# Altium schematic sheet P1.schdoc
size 297 x 209 mm; Symbol: Drawing-Symbol_A4; @Project Name: pcbwatch; @Page Count: 1; @Update Date: 2026-05-27; @Create Date: 2026-05-20; @Schematic Name: Schematic1; @Page No: 1; @Page Name: P1; Company: EasyEDA.com; Version: V1.0; Page Size: A4; @Create Time: 13:10:33; @Update Time: 00:51:18; Border: 1; Width: 1170; Height: 825; Region Start: 1; X Region Count: 6; Y Region Count: 4; Blade Width: 10; Title Block Position: 3; @Board Name: Board1; Device: Drawing-Symbol_A4
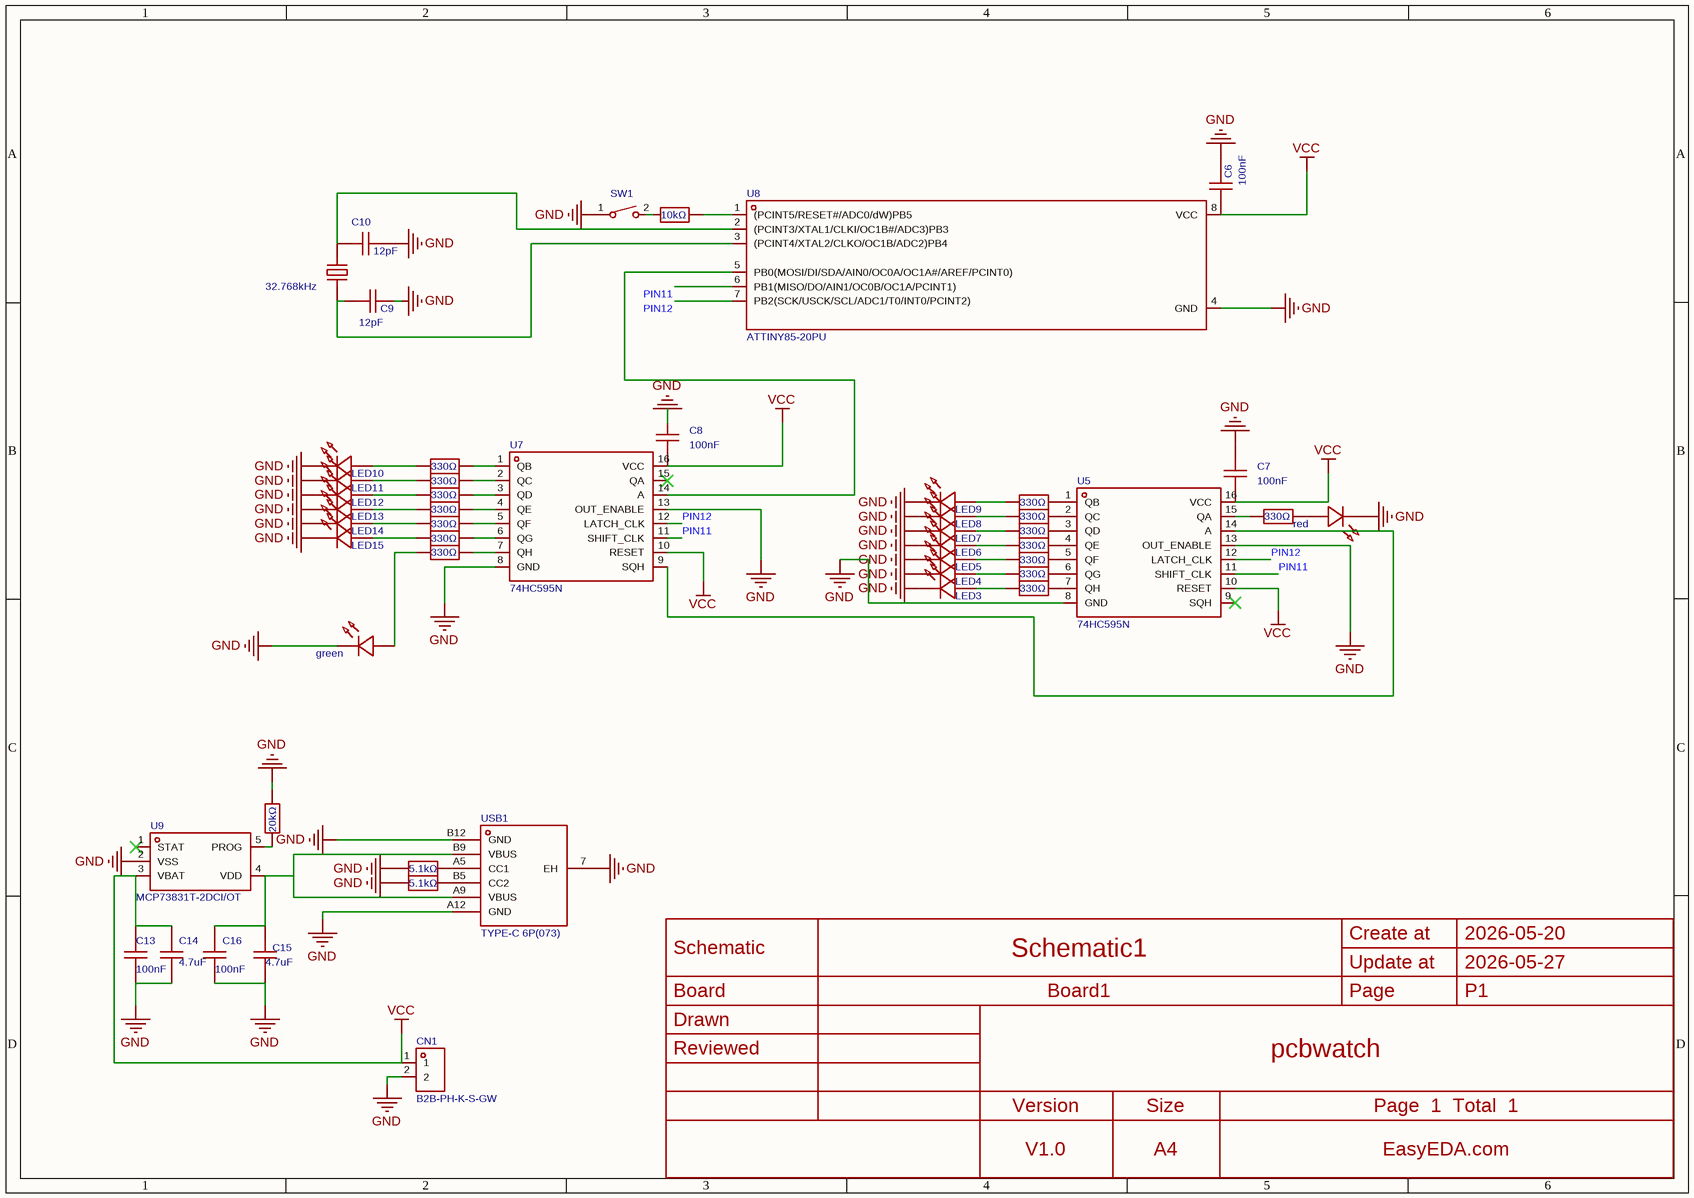
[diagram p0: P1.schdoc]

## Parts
C6  100nF  [CAP-TH_L5.8-W2.4-P2.54-D0.6]
C7  100nF  [CAP-TH_L5.8-W2.4-P2.54-D0.6]
C8  100nF  [CAP-TH_L5.8-W2.4-P2.54-D0.6]
C9  12pF  [CAP-TH_L5.8-W2.4-P2.54-D0.6]
C10  12pF  [CAP-TH_L5.8-W2.4-P2.54-D0.6]
C13  100nF  [CAP-TH_L5.8-W2.4-P2.54-D0.6]
C14  4.7uF  [CAP-TH_L5.8-W2.4-P2.54-D0.6]
C15  4.7uF  [CAP-TH_L5.8-W2.4-P2.54-D0.6]
C16  100nF  [CAP-TH_L5.8-W2.4-P2.54-D0.6]
CN1  B2B-PH-K-S-GW  [CONN-TH_B2B-PH-K-S]
green  TJ-S2012EX8T5ALC2R-A5  [LED0805-RD]  (value not drawn)
LED3  TJ-S2012EX8T5ALC2R-A5  [LED0805-RD]  (value not drawn)
LED4  TJ-S2012EX8T5ALC2R-A5  [LED0805-RD]  (value not drawn)
LED5  TJ-S2012EX8T5ALC2R-A5  [LED0805-RD]  (value not drawn)
LED6  TJ-S2012EX8T5ALC2R-A5  [LED0805-RD]  (value not drawn)
LED7  TJ-S2012EX8T5ALC2R-A5  [LED0805-RD]  (value not drawn)
LED8  TJ-S2012EX8T5ALC2R-A5  [LED0805-RD]  (value not drawn)
LED9  TJ-S2012EX8T5ALC2R-A5  [LED0805-RD]  (value not drawn)
LED10  TJ-S2012EX8T5ALC2R-A5  [LED0805-RD]  (value not drawn)
LED11  TJ-S2012EX8T5ALC2R-A5  [LED0805-RD]  (value not drawn)
LED12  TJ-S2012EX8T5ALC2R-A5  [LED0805-RD]  (value not drawn)
LED13  TJ-S2012EX8T5ALC2R-A5  [LED0805-RD]  (value not drawn)
LED14  TJ-S2012EX8T5ALC2R-A5  [LED0805-RD]  (value not drawn)
LED15  TJ-S2012EX8T5ALC2R-A5  [LED0805-RD]  (value not drawn)
R20  330Ω  [RES-TH_BD2.3-L6.5-P10.50-D0.5]
R21  330Ω  [RES-TH_BD2.3-L6.5-P10.50-D0.5]
R22  330Ω  [RES-TH_BD2.3-L6.5-P10.50-D0.5]
R23  330Ω  [RES-TH_BD2.3-L6.5-P10.50-D0.5]
R24  330Ω  [RES-TH_BD2.3-L6.5-P10.50-D0.5]
R25  330Ω  [RES-TH_BD2.3-L6.5-P10.50-D0.5]
R26  330Ω  [RES-TH_BD2.3-L6.5-P10.50-D0.5]
R27  330Ω  [RES-TH_BD2.3-L6.5-P10.50-D0.5]
R28  330Ω  [RES-TH_BD2.3-L6.5-P10.50-D0.5]
R29  330Ω  [RES-TH_BD2.3-L6.5-P10.50-D0.5]
R30  330Ω  [RES-TH_BD2.3-L6.5-P10.50-D0.5]
R31  330Ω  [RES-TH_BD2.3-L6.5-P10.50-D0.5]
R32  330Ω  [RES-TH_BD2.3-L6.5-P10.50-D0.5]
R33  330Ω  [RES-TH_BD2.3-L6.5-P10.50-D0.5]
R34  330Ω  [RES-TH_BD2.3-L6.5-P10.50-D0.5]
R36  10kΩ  [RES-TH_BD2.3-L6.5-P10.50-D0.5]
R40  20kΩ  [RES-TH_BD2.3-L6.5-P10.50-D0.5]
R41  5.1kΩ  [RES-TH_BD2.3-L6.5-P10.50-D0.5]
R42  5.1kΩ  [RES-TH_BD2.3-L6.5-P10.50-D0.5]
red  TJ-S2012EX8T5ALC2R-A5  [LED0805-RD]  (value not drawn)
SW1  HX 3x4x2-2P-1.6N TACTILE SWITCH  [KEY-SMD_L4.0-W3.0-LS4.9-1]  (value not drawn)
U5  74HC595N  [DIP-16_L19.8-W6.5-P2.54-LS7.6-BL]
U7  74HC595N  [DIP-16_L19.8-W6.5-P2.54-LS7.6-BL]
U8  ATTINY85-20PU  [PDIP-8_L9.3-W6.4-P2.54-LS7.9-BL-1]
U9  MCP73831T-2DCI/OT  [SOT-23-5_L2.9-W1.6-P0.95-LS2.8-BL]
USB1  TYPE-C 6P(073)  [TYPE-C-SMD_TYPE-C-6P-073]
X1  32.768kHz  [OSC-TH_BD2.0-P0.70-D0.3]

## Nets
GND: C6.2 C7.2 C8.1 C9.1 C10.1 C13.2 C14.2 C15.2 C16.2 CN1.2 green.1(C) LED3.1(C) LED4.1(C) LED5.1(C) LED6.1(C) LED7.1(C) LED8.1(C) LED9.1(C) LED10.1(C) LED11.1(C) LED12.1(C) LED13.1(C) LED14.1(C) LED15.1(C) R40.2 R41.2 R42.2 red.1(C) SW1.1 U5.8(GND) U5.13(OUT_ENABLE) U7.8(GND) U7.13(OUT_ENABLE) U8.4(GND) U9.2(VSS) USB1.7(EH) USB1.A12(GND) USB1.B12(GND)
VCC: C6.1 C7.1 C8.2 C13.1 C14.1 CN1.1 U5.10(RESET) U5.16(VCC) U7.10(RESET) U7.16(VCC) U8.8(VCC) U9.3(VBAT)
PIN11: U5.11(SHIFT_CLK) U7.11(SHIFT_CLK) U8.6(PB1(MISO/DO/AIN1/OC0B/OC1A/PCINT1))
PIN12: U5.12(LATCH_CLK) U7.12(LATCH_CLK) U8.7(PB2(SCK/USCK/SCL/ADC1/T0/INT0/PCINT2))
NetC9_2: C9.2 U8.3((PCINT4/XTAL2/CLKO/OC1B/ADC2)PB4) X1.1
NetC10_2: C10.2 U8.2((PCINT3/XTAL1/CLKI/OC1B#/ADC3)PB3) X1.2
NetC15_1: C15.1 C16.1 U9.4(VDD) USB1.A9(VBUS) USB1.B9(VBUS)
Netgreen_2: green.2(A) R26.1
NetLED3_2: LED3.2(A) R33.1
NetLED4_2: LED4.2(A) R32.1
NetLED5_2: LED5.2(A) R31.1
NetLED6_2: LED6.2(A) R30.1
NetLED7_2: LED7.2(A) R29.1
NetLED8_2: LED8.2(A) R28.1
NetLED9_2: LED9.2(A) R27.1
NetLED10_2: LED10.2(A) R20.1
NetLED11_2: LED11.2(A) R21.1
NetLED12_2: LED12.2(A) R22.1
NetLED13_2: LED13.2(A) R23.1
NetLED14_2: LED14.2(A) R24.1
NetLED15_2: LED15.2(A) R25.1
NetR20_2: R20.2 U7.1(QB)
NetR21_2: R21.2 U7.2(QC)
NetR22_2: R22.2 U7.3(QD)
NetR23_2: R23.2 U7.4(QE)
NetR24_2: R24.2 U7.5(QF)
NetR25_2: R25.2 U7.6(QG)
NetR26_2: R26.2 U7.7(QH)
NetR27_2: R27.2 U5.1(QB)
NetR28_2: R28.2 U5.2(QC)
NetR29_2: R29.2 U5.3(QD)
NetR30_2: R30.2 U5.4(QE)
NetR31_2: R31.2 U5.5(QF)
NetR32_2: R32.2 U5.6(QG)
NetR33_2: R33.2 U5.7(QH)
NetR34_1: R34.1 U5.15(QA)
NetR34_2: R34.2 red.2(A)
NetR36_1: R36.1 SW1.2
NetR36_2: R36.2 U8.1((PCINT5/RESET#/ADC0/dW)PB5)
NetR40_1: R40.1 U9.5(PROG)
NetR41_1: R41.1 USB1.A5(CC1)
NetR42_1: R42.1 USB1.B5(CC2)
NetU5_14: U5.14(A) U7.9(SQH)
NetU7_14: U7.14(A) U8.5(PB0(MOSI/DI/SDA/AIN0/OC0A/OC1A#/AREF/PCINT0))

Not connected (* = marked no-connect by the designer): U5 9(SQH)*; U7 15(QA)*; U9 1(STAT)*

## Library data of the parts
C6-C10 C13-C16 = CC1H104ZA1ED3F5P1100: Capacitance:100nF Tolerance:-20%~+80% Tolerance:-20%~+80% Voltage Rating:50V Pin Spacing:2.54mm Temperature Coefficient:Y5V Diameter:5.8mm Body Thickness:2.4mm; Manufacturer: Dersonic(德尔创); AddInBom: yes; ModelId: 87a85daec8c24e17afa0919ab058f76f; ModelTransform: 227.942,104.6505,0,0,0,0,0,0,-196.85; Voltage Rating: 50V; Pin Spacing: 2.54mm; Temperature Coefficient: Y5V; Body Thickness: 2.4mm
CN1 = B2B-PH-K-S-GW: Pins Structure:1x2P Pitch:2mm Mounting Type:Through Hole Reference Series:PH Number of Pins:2P Number of Rows:1 Number of PINs Per Row:2 Row Spacing:- Current Rating:2A Contact Material:Brass Contact Plating:Tin Operating Temperature:-25℃~+85℃ Operating T; Manufacturer: JST; AddInBom: yes; ModelId: 5cc63648eb1041ff813a836ee0942c91; ModelName: CONN-TH_PH2.00-LI-2P; ModelTransform: 236.25937,181.102,0,180,0,0,0,23.622,-137.795; Pins Structure: 1x2P; Pitch: 2mm; Reference Series: PH; Number of PINs Per Row: 2; Current Rating: 2A; Voltage Rating: 100V; Plastic Material: PA66; Flame Retardant Rating: UL94V-0; Supplementary Features: K Pin; Z-Height of the Board: 6mm; X-Length of Bottom Edge on Board (Spacing Line): 5.9mm; Y-Width of Bottom Edge on Board: 4.5mm
green LED3-LED15 red = TJ-S2012EX8T5ALC2R-A5: Lamp Holder Type:2mm x 1.25mm square LED Illumination Color:Red Voltage - Forward(Vf):1.8V~2.4V Voltage - Forward(Vf):1.8V~2.4V Power(Watts):48mW Forward Current:20mA Wavelength - Dominant:620nm~630nm Wavelength - Dominant:620nm~630nm Peak Wavelength:631n; Manufacturer: TOGIALED(统佳); AddInBom: yes; ModelId: 23093642268545519703b953fc993978; ModelTransform: 79.527,49.2125,0,0,0,0,0,0,0; Illumination Color: Red; Power(Watts): 48mW; Forward Current: 20mA; Peak Wavelength: 631nm; Diode Configuration: Discrete Diode; Lens Color: Water Clear; Luminous Intensity: 200mcd; Viewing Angle: 120°
R20-R34 R36 R40-R42 = MF1/4W-1KΩ±1%T52: Type:Metal Film Resistors Resistance: Tolerance:±1% Tolerance:±1% Power(Watts):250mW Temperature Coefficient:±200ppm/℃ Temperature Coefficient:±200ppm/℃; Manufacturer: 华星机电; AddInBom: yes; ModelId: f10e09c7dbfa4e279658667a3edbbac9; ModelName: RES-TH_D2.3-L6.5-P10.50; ModelTransform: 431.1015,91.3384,0,0,0,0,0.197,0,-137.795; Tolerance: ±1%; Power(Watts): 250mW
SW1 = HX 3x4x2-2P-1.6N TACTILE SWITCH: Circuit:SPST Actuator Style:Round Button Operating Force:1.6N Mounting Type:Surface Mount,Vertical Length:4mm Width:3mm Switch Height:2mm with Bracket:Without Bracket Contact Current:50mA Voltage Rating:12V Actuator/Cap Color:Black With Lamp:No IP Rating:; Manufacturer: hanxia(韩下); AddInBom: yes; ModelId: 154383a02d42455f875c495d688faa8c; ModelName: KEY-SMD_L4.0-W3.0-LS4.9; ModelTransform: 188.976,114.173,0,0,0,0,0,0,-17.717; Circuit: SPST; Operating Force: 1.6N; Switch Height: 2mm; Contact Current: 50mA; Voltage Rating: 12V; Actuator/Cap Color: Black; With Lamp: No; Life: 100,000 Cycles
U5 U7 = 74HC595N: Function:Serial-to-Serial or Parallel Voltage - Supply:2V~6V Voltage - Supply:2V~6V Clock Frequency:28MHz Number of Elements:1 Number of Bits per Element:8 Output Type:Tri-State Series:74HC Operating Temperature:-55℃~+125℃ Operating Temperature:-55℃~+125℃; Manufacturer: HTC; Symbol: 74HC595N_C669328; AddInBom: yes; ModelId: c24a9876abec4714888ca3e3d8d19859; ModelName: DIP-16_L20.0-W6.4-H3.5-LS7.62-P2.54; ModelTransform: 787.4,311.8104,0,0,0,0,-0.003,0.001,-118.11; Voltage - Supply: 2V~6V; Clock Frequency: 28MHz; Number of Elements: 1; Number of Bits per Element: 8
U8 = ATTINY85-20PU: CPU Core:AVR CPU Maximum Speed:20MHz Core Size:8 Bit Program Storage Size:8KB Program Memory Type:FLASH RAM Size:512Byte EEPROM:512Byte Number of I/O:6 ADC (Bit):10bit Oscillator Type:Built-in Voltage - Supply:2.7V~5.5V Voltage - Supply:2.7V~5.5V Operatin; Manufacturer: MICROCHIP(美国微芯); AddInBom: yes; ModelId: 0a905fe212f04dd58d97e47ae0145e08; ModelTransform: 366.141,322.834,0,0,0,0,0,0,-118.11; CPU Core: AVR; CPU Maximum Speed: 20MHz; Core Size: 8 Bit; Program Storage Size: 8KB; Program Memory Type: FLASH; Number of I/O: 6; ADC (Bit): 10bit
U9 = MCP73831T-2DCI/OT: The Chip Type:Charging IC Voltage - Supply:3.75V~6V Voltage - Supply:3.75V~6V Charge Current - Max:550mA Charging Saturation Voltage:4.2V End-Off Voltage:- Type of Battery:Lithium Battery Number of Cells:1 Number of Cells:1 Operating Temperature:-40℃~+85℃; Manufacturer: MICROCHIP(美国微芯); AddInBom: yes; ModelId: 181cd81bc0eb45c3a4928013d5e38870; ModelTransform: 114.96,110.236,0,0,0,0,0,0,0; Charge Current - Max: 550mA; Charging Saturation Voltage: 4.2V; Number of Cells: 1; Battery Temperature Detection: Not supported; Supply Current (Iq): 53uA
USB1 = TYPE-C 6P(073): Connector Type:Type-C Protocol Standard:- Gender:Female Mounting Type:Surface Mount, Right Angle Number of Contacts:6P Number of Ports:1 Current Rating-Power:3A Voltage Rating:5V Connect-Disconnect Life:10,000 Cycles Supplementary Features:- Center Height; Manufacturer: SHOU HAN(首韩); AddInBom: yes; ModelId: 5572357f2a5242b0b12e4512f7b213ab; ModelTransform: 351.968,281.49546,0,0,0,0,0.002,-46.967,-39.37; Gender: Female; Number of Ports: 1; Current Rating-Power: 3A; Voltage Rating: 5V; Detection color: Black
X1 = TAXD32768K2BGBBZT2S: Type:Through Hole Crystal Oscillator Frequency:32.768kHz Normal temperature Frequency Tolerance:±10ppm Normal temperature Frequency Tolerance:±10ppm Load Capacitance:12.5pF Frequency Stability:±20ppm Frequency Stability:±20ppm Equivalent Series Resistance; Manufacturer: YJX(雅晶鑫); AddInBom: yes; ModelId: 15f389f4fb4441519db611454debe3ce; ModelName: OSC-TH_D2.0-W6.0-P0.70; ModelTransform: 301.1805,78.66071,0,0,0,0,-144.685,0,-135.8265; Normal temperature Frequency Tolerance: ±10ppm; Load Capacitance: 12.5pF; Frequency Stability: ±20ppm; Equivalent Series Resistance(ESR): 40kΩ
